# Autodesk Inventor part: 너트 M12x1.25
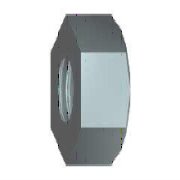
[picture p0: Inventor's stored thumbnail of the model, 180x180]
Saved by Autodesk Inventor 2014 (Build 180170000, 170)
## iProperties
IsCustomPart: 0
Created: 2015-12
Part Number: 너트 M12x1.25
Material: 스테인리스강
Description: 6각 너트
Document SubType Name: Modeling
Standard: KS B 1012
Designer: mdu
Standards Organization: KS
Language: ko-KR
Size Designation: M12x1.25
Categories: <MemberInstance><Categories><Category DisplayName="조임쇠" InternalName="e4da775c-781d-43d5-af7c-5136215cf5a6" Mnemonic="FSTN"><Category DisplayName="너트" InternalN
Density: 8.08 g/cm^3
Mass: 17.9325 g
Surface Area: 14.0653 cm^2
Volume: 2.21937 cm^3
Appearance: 반광택
Author: mdu
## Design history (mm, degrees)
sketch "스케치1"
  geometry: L1 (10.97, 0)-(5.485, -9.5); L2 (5.485, -9.5)-(-5.485, -9.5); L3 (-5.485, -9.5)-(-10.97, 0); L4 (-10.97, 0)-(-5.485, 9.5); L5 (-5.485, 9.5)-(5.485, 9.5); L6 (5.485, 9.5)-(10.97, 0); 2 further points
  constraints: 12 end point, 1 coincident, 1 horizontal, 11 other
  dimensions: "d0" = 21.93931 distance of L1.start L3.end (= 1.1547 x SW)
extrude "본체" new body sketch "스케치1" distance "d1" = 10 (= KOH); taper "d2" = 0 deg
sketch "스케치2"
  geometry: 1 further point
hole "스레드" sketch "스케치2" diameter "d6" = 10.647; stored, may be unused: countersink angle "d10" = 82 deg, drill point angle "d12" = 118 deg; dims "d7" = 12.7, "d8" = 9.525, "d9" = 6.35, "d11" = 19.05
sketch "스케치3"
  geometry: L1 (0, 10.97)-(10, 10.97) reference; L2 (10, 5.485)-(10, 10.97) reference; L3 (-2, 0)-(12, 0) reference; L4 (9.151, 10.97)-(10, 9.5)
  constraints: 2 end point, 2 point on line
  dimensions: "d3" = 19 diameter of L4.end L3 (= SW01); "d4" = 30 deg angle of L2 L4 (= ANG2)
revolve "모따기3" sketch "스케치3" stored, may be unused: angle "d5" = 90 deg
workaxis "Work Axis1"
workplane "Work Plane1"
body "Solid1"
chamfer "모따기1" distance "d13" = 0.67658 (= -0.5 x GD1 + 0.5 x NND); stored, may be unused: angle "d14" = 30 deg, second distance "d21" = 0.67658 (= -0.5 x GD1 + 0.5 x NND)
chamfer "모따기2" distance "d15" = 0.67658 (= -0.5 x GD1 + 0.5 x NND); stored, may be unused: angle "d16" = 30 deg, second distance "d22" = 0.67658 (= -0.5 x GD1 + 0.5 x NND)
other parameters: "ANG2" = 30 deg [user parameter; used in 1 equation term], "NND" = 12 [user parameter; used in 4 equation terms], "KOH" = 10 [user parameter; used in 1 equation term], "SW" = 19 [user parameter; used in 3 equation terms], "SW01" = 19 (= SW) [user parameter; used in 1 equation term], "GD1" = 10.64684 (computed from THREADDIA, PTC, TOA) [user parameter; used in 4 equation terms], "d19" = 0, "d20" = 0, "d24" = 0, "d25" = 0, "GUL" = 0.67658 (= 0.541266 x PTC) [user parameter], "TPU" = 8 (computed from PTC) [user parameter], "TOA" = 30 deg [user parameter; used in 1 equation term], "PTC" = 1.25 [user parameter; used in 4 equation terms], "E0" = 21.945 (= 1.155 x SW) [user parameter], "THREADDIA" = 12 [user parameter; used in 1 equation term], "GAL" = 0.67658 (= 0.541266 x PTC) [user parameter]
